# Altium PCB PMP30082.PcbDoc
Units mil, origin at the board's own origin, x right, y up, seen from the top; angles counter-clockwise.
Board outline 2800 x 3100 mil, 2 copper layers (Top Layer, Bottom Layer), stack 62 mil thick; 55 components, 28 nets, 134 pads, 39 vias.
Unrouted connection lines stored in the file: 1.
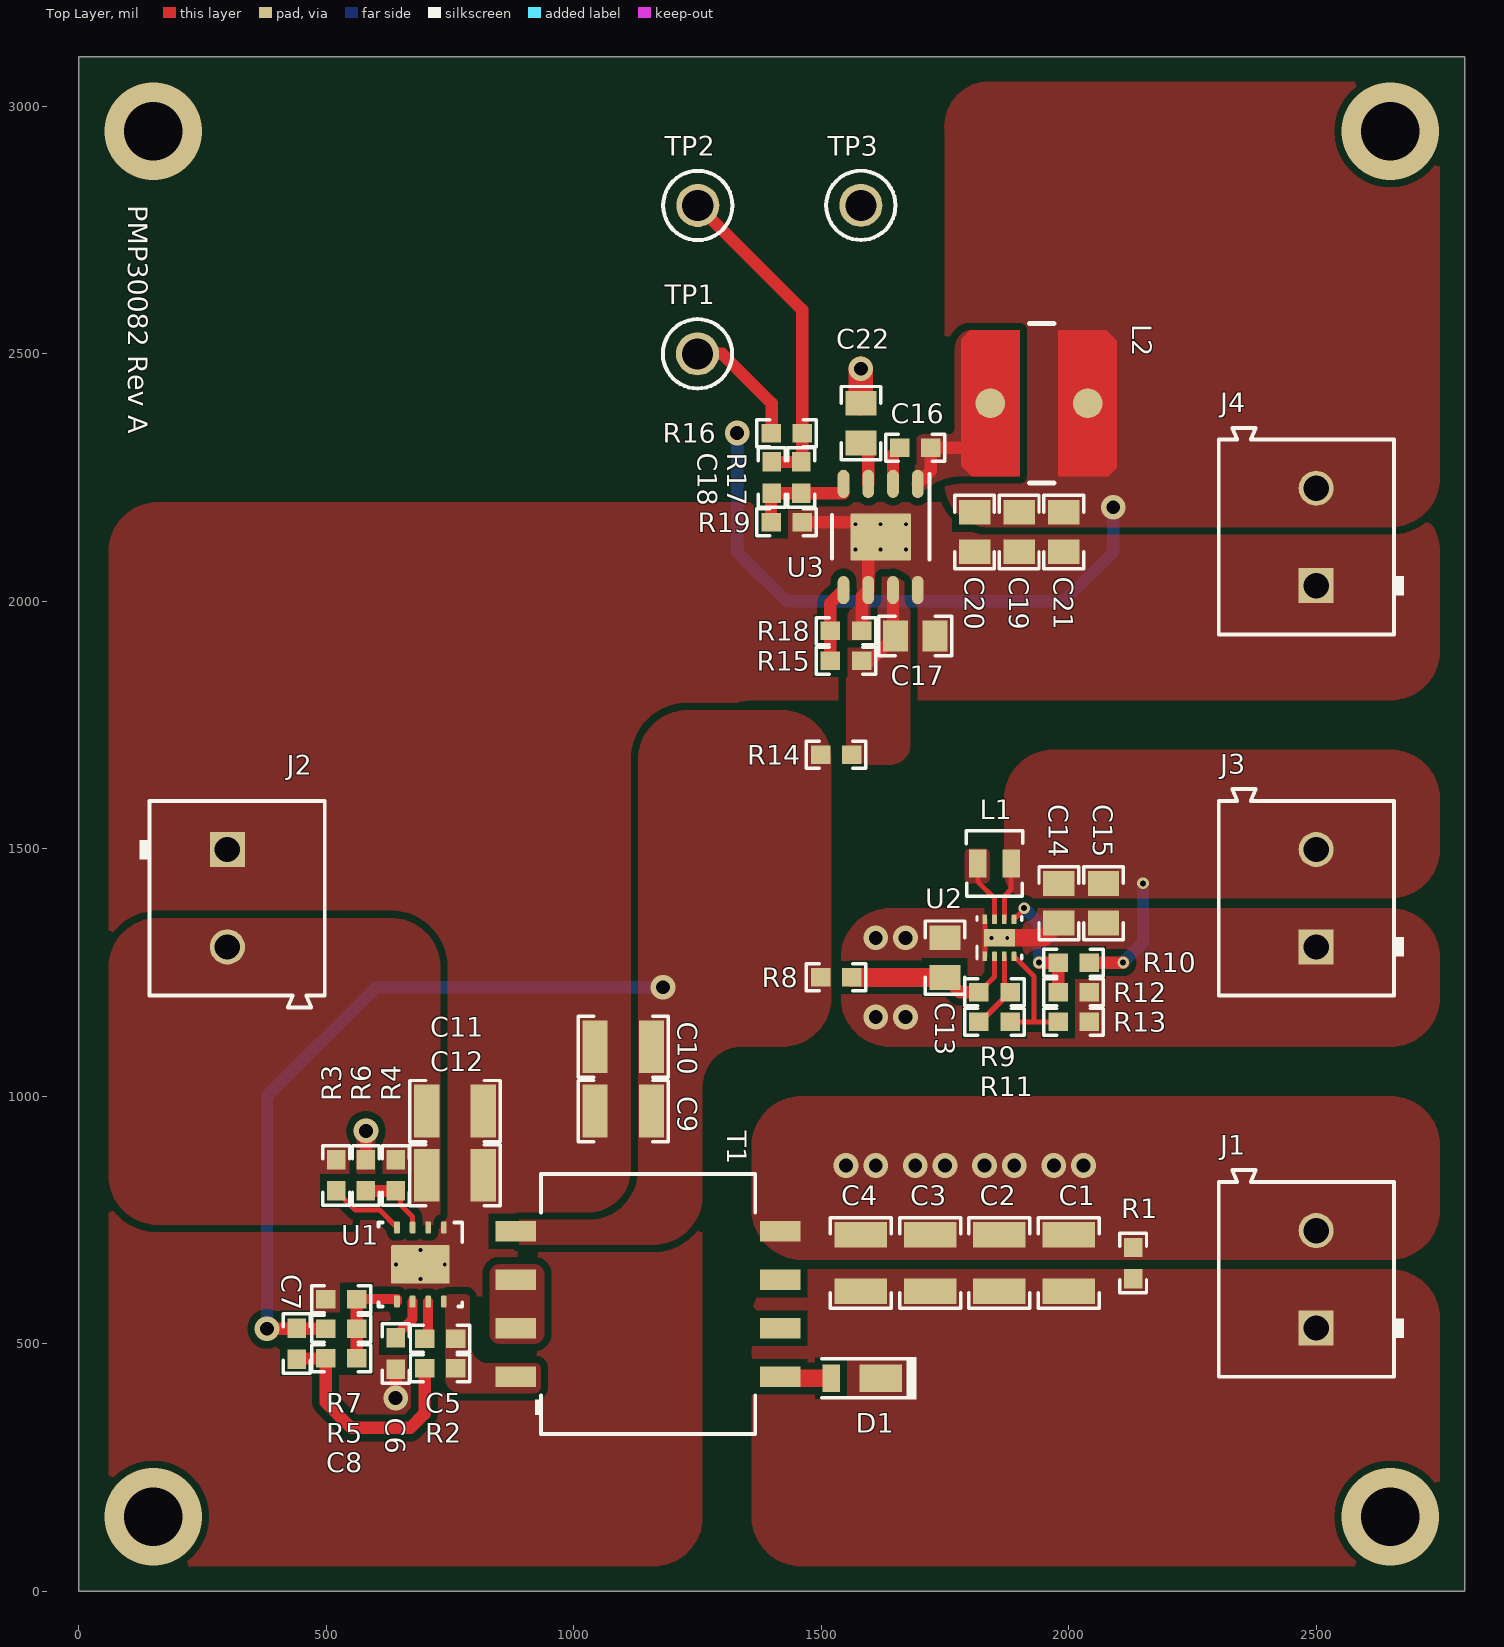
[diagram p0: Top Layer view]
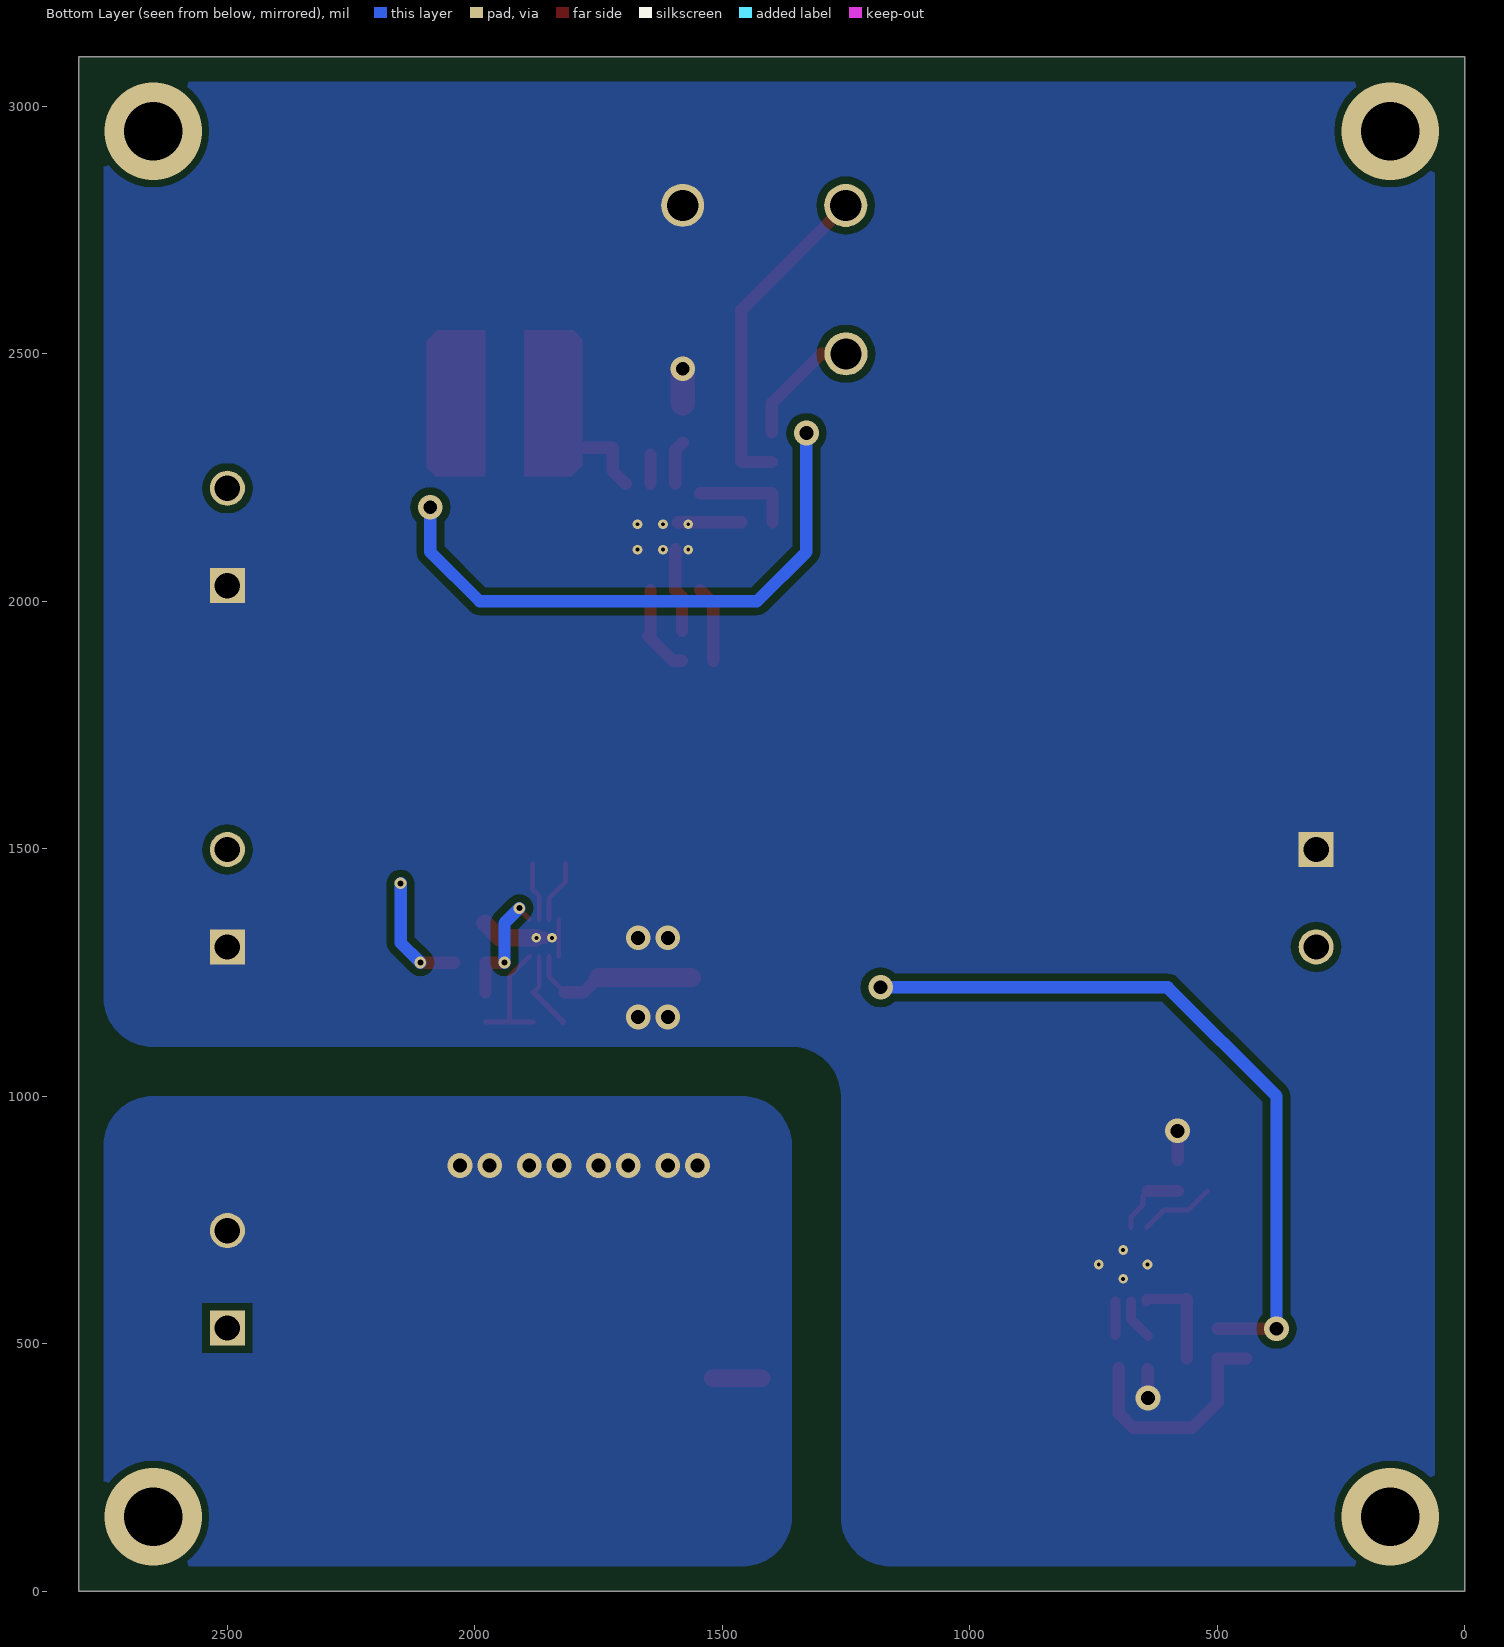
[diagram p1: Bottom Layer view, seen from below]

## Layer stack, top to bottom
Top Solder: solder mask 0.4, Solder Resist, Dk 3.5
Top Layer: signal copper 1.4
Dielectric1: core 59.2, FR-4, Dk 4.8
Bottom Layer: signal copper 1.4
Bottom Solder: solder mask 0.4, Solder Resist, Dk 3.5

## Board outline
0,3100 2800,3100 2800,0 0,0 0,3100

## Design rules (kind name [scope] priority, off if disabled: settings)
AcuteAngle [All] p1: minimum=4.50000000000000E+0001 checktracksonly=FALSE
AssemblyTestPointUsage [All] p1: valid=2
Clearance Clearance_Keepouts [((IsTrack Or IsArc) And Not InPoly) And IsFree and IsKeepOut vs ((IsTrack Or IsArc) And Not InPoly) And IsFree and IsKeepOut] p1: gap=0
Clearance Clearance_BoardEdge_MountingHoles [OnCopper and InComponentClass('Mounting Holes') vs IsKeepOut] p2: gap=40
Clearance Clearance_BoardEdge_Poly [OnCopper and InPoly vs IsKeepOut] p3: gap=25
Clearance Clearance_BoardEdge [OnCopper and Not InComponentClass('Logo') and not InComponentClass('FiducialMark') and not InRegion(1000,500,4000,800) and Not IsKeepout vs IsKeepOut] p4: gap=75
Clearance Clearance_Poly [InPolygon] p5: gap=15
Clearance [All] p6: gap=7.87
ComponentClearance ComponentClearance_MountingHoles_FiducialMarks [InComponentClass('Mounting Holes') vs InComponentClass('FiducialMark')] p1: gap=50 collisioncheckmode=3 verticalgap=10 showdistances=FALSE
ComponentClearance ComponentClearance_Shunt [InComponentClass('Header') vs InComponentClass('Shunt')] p2: gap=0 collisioncheckmode=3 verticalgap=0 showdistances=FALSE
ComponentClearance ComponentClearance_Logo [InComponentClass('Logo')] p3: gap=50 collisioncheckmode=3 verticalgap=10 showdistances=FALSE
ComponentClearance ComponentClearance_ScrewToNut [(HasFootprint('NY PMS 440 0025 PH')) vs (HasFootprint('Keystone_1902C'))] p4: gap=5 collisioncheckmode=3 verticalgap=10 showdistances=FALSE
ComponentClearance ComponentClearance_MountingHoles [InComponentClass('Mounting Holes')] p5: gap=250 collisioncheckmode=3 verticalgap=100000 showdistances=FALSE
ComponentClearance ComponentClearance_SmallPassives [HasFootprint('0201*') or HasFootprint('0402*') or HasFootprint('0508') or HasFootprint('0603*') or HasFootprint('0612') or HasFootprint('0805*') or HasFootprint('0815*') or HasFootprint('0830*') or HasFootprint('1206*') or HasFootprint('1210*') or HasFootprint('1808*') or HasFootprint('1812*') or HasFootprint('1825*') or HasFootprint('2010*') or HasFootprint('2220*') or HasFootprint('2225*') or HasFootprint('2512*') or HasFootprint('2728*') or HasFootprint('3518*') vs HasFootprint('0201*') or HasFootprint('0402*') or HasFootprint('0508') or HasFootprint('0603*') or HasFootprint('0612') or HasFootprint('0805*') or HasFootprint('0815*') or HasFootprint('0830*') or HasFootprint('1206*') or HasFootprint('1210*') or HasFootprint('1808*') or HasFootprint('1812*') or HasFootprint('1825*') or HasFootprint('2010*') or HasFootprint('2220*') or HasFootprint('2225*') or HasFootprint('2512*') or HasFootprint('2728*') or HasFootprint('3518*')] p6: gap=20 collisioncheckmode=3 verticalgap=10 showdistances=FALSE
ComponentClearance ComponentClearance_THtoSMT [IsThruComponent vs IsSMTComponent] p7: gap=100 collisioncheckmode=3 verticalgap=30 showdistances=FALSE
ComponentClearance ComponentClearance_THtoTH [IsThruComponent vs IsThruComponent] p8: gap=118.11 collisioncheckmode=3 verticalgap=30 showdistances=FALSE
ComponentClearance [All] p9: gap=40 collisioncheckmode=3 verticalgap=10 showdistances=FALSE
DiffPairsRouting [All] p1: maxlimit=100 minlimit=10 mostfreqgap=10 toplayer_minwidth=15 toplayer_maxwidth=15 toplayer_prefwidth=15 bottomlayer_minwidth=15 bottomlayer_maxwidth=15 bottomlayer_prefwidth=15 maxuncoupledlength=1000
FabricationTestPointUsage TestPointUsage [All] p1: valid=2 allowmultiple=FALSE
FabricationTestpoint Testpoint [All] p1: side=3 testpointundercomponent=TRUE minsize=40 maxsize=100 preferedsize=60 minholesize=0 maxholesize=40 preferedholesize=32 testpointgrid=1 allowsidetop=TRUE allowsidebottom=TRUE usegrid=TRUE gridtolerance=0.01
FanoutControl Fanout_LCC [IsLCC] p1: bgadir=Out bgaviamode=Centered fanoutstyle=Auto fanoutdirection=Alternating viagrid=1 // Fanout_LCC (Default Rule)
FanoutControl Fanout_BGA [IsBGA] p2: bgadir=Out bgaviamode=Centered fanoutstyle=Auto fanoutdirection=Alternating viagrid=1 // Fanout_BGA (Default Rule)
FanoutControl Fanout_Default [All] p4: bgadir=Out bgaviamode=Centered fanoutstyle=Auto fanoutdirection=Alternating viagrid=1 // Fanout_Default (Default Rule)
FanoutControl Fanout_Small [(CompPinCount < 5)] p5: bgadir=Out bgaviamode=Centered fanoutstyle=Auto fanoutdirection=OutThenIn viagrid=1 // Fanout_Small (Default Rule)
HoleSize [All] p1: absolutevalues=TRUE maxlimit=251 minlimit=8 maxpercent=80.000 minpercent=20.000
MinimumAnnularRing MinimumAnnularRing_ThermalPadVias [IsVia and InAnyComponent] p1: minimumring=5.91
MinimumAnnularRing [All] p2: minimumring=9
MinimumSolderMaskSliver MinimumSolderMaskSliver_Logo [InComponentClass('Logo') vs InComponentClass('Logo')] p1: minsoldermaskwidth=0.7
MinimumSolderMaskSliver [All] p2: minsoldermaskwidth=3.94
PlaneConnect [All] p1: planeconnectstyle=Relief reliefexpansion=10 reliefentries=4 reliefconductorwidth=10 reliefairgap=10
PolygonConnect [All] p1: connectstyle=Direct reliefconductorwidth=10 reliefentries=4 polygonreliefangle="90 Angle" airgapwidth=10
RoutingVias ThermalPadVias [IsVia and InAnyComponent] p1: holewidth=7.87 width=19.68 viastyle="Through Hole" minholewidth=7.87 minwidth=19.68 maxholewidth=12.99 maxwidth=23.62
RoutingVias [All] p2: holewidth=16 width=34 viastyle="Through Hole" minholewidth=7.87 minwidth=26 maxholewidth=40 maxwidth=65
SilkToBoardRegionClearance [Not ((IsComment or IsDesignator) And (Hide <> 'False')) and not InRegion(1000,500,4000,800)] p1:
SilkToSilkClearance SilkToSilkClearance_Pb-FreeLogo [(HasFootprint('Pb-Free_Overlay_Medium') OR HasFootprint('Pb-Free_Overlay_Small')) vs (HasFootprint('Pb-Free_Overlay_Medium') OR HasFootprint('Pb-Free_Overlay_Small'))] p1: silktosilkclearance=0
SilkToSilkClearance [All] p2: silktosilkclearance=4
SilkToSolderMaskClearance SilkToComonentPadClearance [IsPad and InAnycomponent] p1: minsilkscreentomaskgap=5 clearancetoexposedcopper=TRUE
SilkToSolderMaskClearance "Silk to Solder Mask Opening" [All] p2: minsilkscreentomaskgap=4 clearancetoexposedcopper=FALSE
SolderMaskExpansion [All] p1: expansion=1.97
Width [All] p1: maxlimit=100 minlimit=6 preferedwidth=10 checkconnectedcopper=TRUE
15 further rules are at their usual default settings.

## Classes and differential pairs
component class "PMP30082_1_RevA - Circuit": C1 C2 C3 C4 C5 C6 C7 C8 C9 C10 C11 C12 D1 J1 J2 R1 R2 R3 R4 R5 R6 R7 T1 U1
component class "PMP30082_2_RevA - Circuit": C16 C17 C18 C19 C20 C21 C22 J4 L2 R14 R15 R16 R17 R18 R19 TP1 TP2 TP3 U3
component class "PMP30082_3_RevA - Circuit": C13 C14 C15 J3 L1 R8 R9 R10 R11 R12 R13 U2

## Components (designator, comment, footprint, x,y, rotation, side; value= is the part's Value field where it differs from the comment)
C1 "GRM32ER61H106KA12L" 1210_270 2000,662.76 r270 top
C2 "GRM32ER61H106KA12L" 1210_270 1860,662.76 r270 top
C3 "GRM32ER61H106KA12L" 1210_270 1720,662.76 r270 top
C4 "GRM32ER61H106KA12L" 1210_270 1580,662.76 r270 top
C5 "GCM188R71H103KA37D" 0603 730,510 r180 top
C6 "GRM188R71C105KA12D" 0603 640,480 r90 top
C7 "GRM188R70J473KA01D" 0603 440,500 r270 top
C8 "GCM188R71H104KA57D" 0603 530,470 r0 top
C9 "GRM32ER61E226KE15L" 1210_270 1100,970 r180 top
C10 "GRM32ER61E226KE15L" 1210_270 1100,1100 r180 top
C11 "GRM32ER72A225KA35L" 1210_270 760,970 r0 top
C12 "GRM32ER72A225KA35L" 1210_270 760,840 r0 top
C13 "GRM21BR61E225KA12L" 0805_HV 1750,1280 r90 top
C14 "GRM21BR70J106KE76L" 0805_HV 1980,1390 r270 top
C15 "GRM21BR70J106KE76L" 0805_HV 2070,1390 r270 top
C16 "GRM188R71C474KA88D" 0603 1690,2310 r180 top
C17 "GRM21BC71E106KE11L" 0805_HV 1690,1930 r0 top
C18 "GRM1885C2A151JA01D" 0603 1400,2250 r270 top
C19 "GRM21BR61A226ME44L" 0805_HV 1900,2140 r270 top
C20 "GRM21BR61A226ME44L" 0805_HV 1810,2140 r270 top
C21 "GRM21BR61A226ME44L" 0805_HV 1990,2140 r270 top
C22 "GRM21BR71C475KA73L" 0805_HV 1580,2360 r90 top
D1 "DFLS1200-7" PowerDI123 1570,430 r180 top
J1 "691 101 710 002" Wurth_691101710002 2500,630 r90 top
J2 "691 101 710 002" Wurth_691101710002 300,1400 r270 top
J3 "691 101 710 002" Wurth_691101710002 2500,1400 r90 top
J4 "691 101 710 002" Wurth_691101710002 2500,2130 r90 top
L1 "VLF302515MT-150M" VLF302515MT 1850,1470 r0 top
L2 "744775147" WE-PD2-L 1940,2400 r0 top
R1 "CRCW060312K1FKEA" 0603 2130,662.76 r90 top
R2 "CRCW060310K0FKEA" 0603 730,450 r180 top
R3 "CRCW0603301KFKEA" 0603 520,840 r270 top
R4 "ERJ-3GEY0R00V" 0603 640,840 r90 top
R5 "CRCW060344K2FKEA" 0603 530,530 r180 top
R6 "CRCW060310K0FKEA" 0603 580,840 r270 top
R7 "CPF0603B4K99E" 0603 530,590 r0 top
R8 "ERJ-3GEY0R00V" 0603 1530,1240 r180 top
R9 "ERJ-3GEY0R00V" 0603 1850,1210 r180 top
R10 "CRCW0603180KJNEA" 0603 2010,1270 r0 top
R11 "ERJ-3GEY0R00V" 0603 1850,1150 r180 top
R12 "CRCW060357K6FKEA" 0603 2010,1210 r180 top
R13 "ERJ-3GEY0R00V" 0603 2010,1150 r180 top
R14 "ERJ-3GEY0R00V" 0603 1530,1690 r180 top
R15 "ERJ-3GEY0R00V" 0603 1550,1880 r180 top
R16 "CRCW060349R9FKEA" 0603 1430,2340 r180 top
R17 "CRCW060349K9FKEA" 0603 1460,2250 r90 top
R18 "ERJ-3GEY0R00V" 0603 1550,1940 r180 top
R19 "CRCW060312K4FKEA" 0603 1430,2160 r180 top
T1 "750370599" Wurth_750370599 1150,580 r90 top
TP1 "5010" Keystone5010 1250,2500 r90 top
TP2 "5014" Keystone5014 1250.5,2799.87 r90 top
TP3 "5011" Keystone5011 1580,2800 r90 top
U1 "LM5017SDX/NOPB" NGU0008B 690,660 r270 top
U2 "TPS62125DSGR" DSG0008A 1860,1320 r90 top
U3 "LMR23610ADDAR" DDA0008E_N 1620,2130 r270 top

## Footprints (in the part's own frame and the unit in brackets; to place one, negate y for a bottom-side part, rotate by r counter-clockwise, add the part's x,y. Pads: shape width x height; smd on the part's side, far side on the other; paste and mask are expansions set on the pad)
0603 [mm] "0603 from SM-752 data"
  rect 1x0.95 smd: 1(-0.8,0) 2(0.8,0)
  silkscreen extent -1.52,-0.69 1.52,0.69, body extent -0.87,-0.47 0.87,0.47, height 1
0805_HV [mil] "0805 with 30mil clearance between pads"
  rect 50x63 smd: 1(-40,0) 2(40,0)
  silkscreen extent -74,-40 74,40, body extent -43,-29 43,29, height 57
1210_270 [mm] "1210"
  rect 1.3x2.7 smd: 1(-1.45,0) 2(1.45,0)
  silkscreen extent -2.32,-1.57 2.32,1.57, body extent -1.7,-1.35 1.7,1.35, height 2.7
DDA0008E_N [mm]
  rrect100% 1.45x0.6 smd: 1(-2.725,1.905) 2(-2.725,0.635) 3(-2.725,-0.635) 4(-2.725,-1.905) 5(2.725,-1.905) 6(2.725,-0.635) 7(2.725,0.635) 8(2.725,1.905)
  rrect4% 2.4x3.1 smd: 9(0,0)
  silkscreen extent -3.22,-2.5 1.15,2.5, body extent -3.01,-2.45 3.01,2.45, height 1.7
DSG0008A [mm] "SON, 8-Leads, Body 2x2mm, Pitch 0.5mm, Thermal Pad 1.6x0.9mm, TI Recommended"
  rrect40% 0.5x0.25 smd: 1(-0.95,0.75) 2(-0.95,0.25) 3(-0.95,-0.25) 4(-0.95,-0.75) 5(0.95,-0.75) 6(0.95,-0.25) 7(0.95,0.25) 8(0.95,0.75)
  rrect11% 0.9x1.6 smd paste-0.45: 9(0,0)
  silkscreen extent -1.07,-1.15 1.07,1.15, body extent -1.05,-1.05 1.05,1.05, height 0.8
Keystone5010 [mil] "Keystone Multipurpose loops"
  round 87 hole 63: 1(0,0)
  silkscreen extent -70,-70 70,70, body extent -63,-63 63,62, height 319
Keystone5011 [mil] "Keystone Multipurpose loops"
  round 87 hole 63: 1(0,0)
  silkscreen extent -70,-70 70,70, body extent -63,-63 63,62, height 319
Keystone5014 [mil] "Keystone Multipurpose loops"
  round 87 hole 63: 1(0,0)
  silkscreen extent -70,-70 70,70, body extent -63,-63 63,62, height 319
NGU0008B [mm] "SON, 8-Leads, Body 4x4mm, Pitch 0.8mm"
  rrect33% 0.6x0.3 smd: 1(-1.9,1.2) 2(-1.9,0.4) 3(-1.9,-0.4) 4(-1.9,-1.2) 5(1.9,-1.2) 6(1.9,-0.4) 7(1.9,0.4) 8(1.9,1.2)
  rrect5% 1.98x3 smd paste-1.5: 9(0,0)
  silkscreen extent -2.15,-2.15 2.15,2.15, body extent -2.05,-2.05 2.05,2.05, height 0.81
PowerDI123 [mm] "Diodes Inc recommended land pattern, document number DS30628 Rev. 6-2"
  rect 2.2x1.4 smd: 1(-1.275,0)
  rect 0.9x1.4 smd: 2(1.275,0)
  silkscreen extent -3.1,-1.09 1.76,1.09, body extent -2.38,-0.97 1.52,0.96, height 1
VLF302515MT [mm] "TDK"
  rect 0.9x1.45 smd: 1(-0.85,0) 2(0.85,0)
  silkscreen extent -1.45,-1.68 1.45,1.68, body extent -1.35,-1.6 1.35,1.6, height 1.5
WE-PD2-L [mil] "WE, Inductor"
  round 60 smd: 1(-98.43,0) 2(98.43,0)
  Top Layer region: 39.37,147.64 39.37,-147.64 139.76,-147.64 157.48,-129.92 157.48,125.98 135.83,147.64
  Top Layer region: -39.37,-147.64 -39.37,147.64 -139.76,147.64 -157.48,129.92 -157.48,-125.98 -135.83,-147.64
  silkscreen extent -20,-161 30,161, body extent -157,-144 159,144, height 217
Wurth_750370599 [mm] "SMD, 8-Leads, Body 15.24x11mm, Pitch 2.49mm"
  rect 1.07x2.08 smd: 1(-3.735,6.78) 2(-1.245,6.78) 3(1.245,6.78) 4(3.735,6.78) 5(3.735,-6.78) 6(1.245,-6.78) 7(-1.245,-6.78) 8(-3.735,-6.78)
  silkscreen extent -6.67,-5.5 6.67,5.8, body extent -6.67,-7.62 6.67,7.62, height 11.44
Wurth_691101710002 [mm] "Terminal Block, 5 mm, 2x1, TH"
  rect 1.8x1.8 hole 1.3: 1(-2.5,0)
  round 1.8 hole 1.3: 2(2.5,0)
  silkscreen extent -5,-4.5 5.6,5, body extent -5.6,-4 5.6,5, height 12.5

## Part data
C1 C2 C3 C4: "CAP, CERM, 10 µF, 50 V, +/- 10%, X5R, 1210"
C5: "CAP, CERM, 0.01 µF, 50 V, +/- 10%, X7R, AEC-Q200 Grade 1, 0603"
C6: "CAP, CERM, 1 µF, 16 V, +/- 10%, X7R, 0603"
C7: "CAP, CERM, 0.047 µF, 6.3 V, +/- 10%, X7R, 0603"
C8: "CAP, CERM, 0.1 µF, 50 V, +/- 10%, X7R, 0603"
C9 C10: "CAP, CERM, 22 µF, 25 V, +/- 10%, X5R, 1210"
C11 C12: "CAP, CERM, 2.2 µF, 100 V, +/- 10%, X7R, 1210"
C13: "CAP, CERM, 2.2 µF, 25 V, +/- 10%, X5R, 0805"
C14 C15: "CAP, CERM, 10 µF, 6.3 V, +/- 10%, X7R, 0805"
C16: "CAP, CERM, 0.47 µF, 16 V, +/- 10%, X7R, 0603"
C17: "CAP, CERM, 10 µF, 25 V, +/- 10%, X7S, 0805"
C18: "CAP, CERM, 150 pF, 100 V, +/- 5%, C0G/NP0, 0603"
C19 C20 C21: "CAP, CERM, 22 µF, 10 V, +/- 20%, X5R, 0805"
C22: "CAP, CERM, 4.7 µF, 16 V, +/- 10%, X7R, 0805"
D1: "Diode, Schottky, 200 V, 1 A, PowerDI123"
J1 J2 J3 J4: "Terminal Block, 5 mm, 2x1, Tin, TH"
L1: "Inductor, Shielded, Ferrite, 15 µH, 0.56 A, 0.275 ohm, SMD"
L2: "Inductor, Shielded Drum Core, Ferrite, 47 µH, 1.17 A, 0.18 ohm, SMD"
R1: "RES, 12.1 k, 1%, 0.1 W, 0603"
R2 R6: "RES, 10.0 k, 1%, 0.1 W, 0603"
R3: "RES, 301 k, 1%, 0.1 W, 0603"
R4 R8 R9 R11 R13 R14 R15 R18: "RES, 0, 5%, 0.1 W, 0603"
R5: "RES, 44.2 k, 1%, 0.1 W, 0603"
R7: "RES, 4.99 k, 0.1%, 0.063 W, 0603"
R10: "RES, 180 k, 5%, 0.1 W, 0603"
R12: "RES, 57.6 k, 1%, 0.1 W, 0603"
R16: "RES, 49.9, 1%, 0.1 W, 0603"
R17: "RES, 49.9 k, 1%, 0.1 W, 0603"
R19: "RES, 12.4 k, 1%, 0.1 W, 0603"
T1: "Transformer, 250 uH, SMT"
TP1: "Test Point, Multipurpose, Red, TH"
TP2: "Test Point, Multipurpose, Yellow, TH"
TP3: "Test Point, Multipurpose, Black, TH"
U1: "100V, 600mA Constant On-Time Synchronous Buck Regulator, NGU0008B"
U2: "3V-17V, 300mA Step Down Converter With Adjustable Enable Threshold And Hysteresis, DSG0008A"
U3: "SIMPLE SWITCHER 36 V, 1 A Synchronous Step-Down Converter, DDA0008E"

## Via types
v1: diameter 50, hole 28, Top Layer to Bottom Layer, 19 vias
v2: diameter 19.68, hole 7.87, Top Layer to Bottom Layer, 6 vias
v3: diameter 19.68, hole 7.87, Top Layer to Bottom Layer, tented top, 6 vias
v4: diameter 23.62, hole 11.81, Top Layer to Bottom Layer, 4 vias
v5: diameter 196.85, hole 118.11, Top Layer to Bottom Layer, 4 vias

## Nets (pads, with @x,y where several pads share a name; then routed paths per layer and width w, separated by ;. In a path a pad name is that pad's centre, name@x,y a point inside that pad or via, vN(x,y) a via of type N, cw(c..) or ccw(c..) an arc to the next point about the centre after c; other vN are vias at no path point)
"3.3V @ 100MA": C14.1 C15.1 J3.2 L1.2 R10.2 U2.6 | length 363.3
  Top Layer w10: U2.6 1869.84,1403.9 1883.46,1417.52 L1.2
  Top Layer w25: R10.2 v4(2110,1270)
  Bottom Layer w25: v4(2110,1270) 2150,1310 v4(2150,1430)
"5V @ 400MA": C19.1 C20.1 C21.1 J4.2 L2.2 R16.2 TP1.1 | length 1422.8
  Top Layer w25: TP1.1 1300,2500 1400,2400 R16.2@1400,2341.5
  Bottom Layer w25: v1(1330,2340) 1330,2100 1430,2000 1990,2000 2090,2100 v1(2090,2190)
"12V @ 250MA": C7.1 C9.1 C10.1 R5.2 R8.2 R14.2 T1.4 | length 1479.6
  Top Layer w25: v1(380,530) R5.2
  Bottom Layer w25: v1(380,530) 380,1000 600,1220 v1(1180,1220)
"24VOUT @ 160MA": C1.2 C2.2 C3.2 C4.2 D1.1 J1.1 R1.1
48-72VIN: C11.1 C12.1 J2.2 R3.1 R4.2 U1.2
GND: C6.1 C9.2 C10.2 C11.2 C12.2 C13.2 C14.2 C15.2 C17.2 C19.2 C20.2 C21.2 C22.2 J2.1 J3.1 J4.1 R6.1 R7.1 R12.1 R13.1 R18.1 R19.1 TP3.1 U1.1 U1.9 U2.1 U2.8 U2.9 U3.6 U3.8 U3.9 | length 722.9
  Top Layer w10: U2.1 U2.9@1830.47,1320 ; U2.8 U2.9@1830.47,1320 ; U2.9 v2(1844.25,1320) U2.9@1830.47,1320
  Top Layer w25: R6.1 v1(580,930) ; v1(640,390) C6.1 ; R19.1 U3.9@1590,2160 ; R18.1 1581.5,2009.21 U3.6 U3.9@1595,2105 ; U2.9 v2(1875.75,1320)
  Top Layer w35: v2(1875.75,1320) 1950,1320 C14.2
  Top Layer w50: C22.2 v1(1580,2470)
  other v1: 1610,1160 1670,1160 1610,1320 1670,1320
  other v2: 690,630.87 640.79,660 739.21,660 690,689.13
  other v3: 1568.82,2104.41 1620,2104.41 1671.18,2104.41 1568.82,2155.59 1620,2155.59 1671.18,2155.59
ISOGND: C1.1 C2.1 C3.1 C4.1 J1.2 R1.2 T1.5
  other v1: 1550,860 1610,860 1690,860 1750,860 1830,860 1890,860 1970,860 2030,860
NetC5_1: C5.1 R2.1 T1.1 U1.8
NetC5_2: C5.2 U1.7 | length 68
  Top Layer w20: C5.2@705.75,517.24 U1.7
NetC6_2: C6.2 U1.6 | length 84.2
  Top Layer w20: C6.2@640,515.16 674.25,549.41 U1.6
NetC7_2: C7.2 C8.1 R2.2 | length 470.1
  Top Layer w25: C7.2@441.5,470 C8.1 498.5,381.5 550,330 670,330 698.5,358.5 R2.2
NetC8_2: C8.2 R5.1 R7.2 U1.5 | length 206.1
  Top Layer w20: R7.2 642.76,590 U1.5
  Top Layer w25: C8.2 R7.2
NetC13_1: C13.1 R8.1 R9.2 U2.2 | length 355.1
  Top Layer w10: R9.2 1850,1241.5 1850,1282.44 U2.2
  Top Layer w25: C13.1 1780,1210 R9.2
  Top Layer w38: R8.1 C13.1
NetC16_1: C16.1 L2.1 U3.1 | length 172.2
  Top Layer w25: U3.1 1721.5,2263.78 C16.1 1810,2310
NetC16_2: C16.2 U3.2 | length 59.2
  Top Layer w25: U3.2 C16.2@1645,2296.5
NetC17_1: C17.1 R14.1 R15.1 U3.7 | length 176.9
  Top Layer w25: R15.1 1600,1880 C17.1 ; C17.1@1645,1935 U3.7
NetC18_1: C18.1 R16.1 R17.2 TP2.1 | length 664.3
  Top Layer w25: TP2.1 1461.5,2588.88 R16.1 R17.2@1461.5,2282.99 ; C18.1 R17.2
NetC18_2: C18.2 R17.1 R19.2 U3.4 | length 204.1
  Top Layer w25: R19.2 1398.5,2217.01 C18.2 R17.1 U3.4@1545,2218.5
NetC22_1: C22.1 U3.3 | length 88.9
  Top Layer w25: C22.1 1595,2305 U3.3
NetD1_2: D1.2 T1.8 | length 99.9
  Top Layer w35: T1.8@1419.88,430 D1.2
NetL1_1: L1.1 U2.7 | length 126.5
  Top Layer w10: L1.1 1816.54,1433.46 1850.16,1399.84 U2.7
NetR3_2: R3.2 U1.4 | length 153.3
  Top Layer w10: R3.2 558.5,770 607.56,770 U1.4
NetR4_1: R4.1 R6.2 U1.3 | length 147.9
  Top Layer w10: R4.1 650,798.5 650,780 674.25,755.75 U1.3
  Top Layer w25: R6.2 R4.1
NetR9_1: R9.1 R11.2 U2.3 | length 162.3
  Top Layer w10: U2.3 1869.84,1221.65 R9.1
  Top Layer w12: R11.2@1821.5,1150 R9.1
NetR10_1: R10.1 R12.2 U2.5 | length 249.9
  Top Layer w10: U2.5 v4@1910,1377.87
  Top Layer w25: v4(1940,1270) R10.1 R12.2
  Bottom Layer w25: v4(1910,1380) 1940,1350 v4(1940,1270)
NetR11_1: R11.1 R13.2 U2.4 | length 246.4
  Top Layer w10: R11.1 1930,1150 ; U2.4 1930,1242.13 1930,1150 ; R13.2 1930,1150
NetR15_2: R15.2 R18.2 U3.5 | length 153.7
  Top Layer w25: R15.2 R18.2 1518.5,1996.22 U3.5
NetT1_2: T1.2 T1.3
pads on no net: T1.6 T1.7
copper on no net:
  other v5: 150,150 2650,150 150,2950 2650,2950

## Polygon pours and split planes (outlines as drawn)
NetL1_1 on Top Layer "NETL1_1_L01_P068" (solid, remove dead copper, pour order 68): 1790,1460 1790,1480 1790,1490 cw(c1800,1490) 1800,1500 1830,1500 cw(c1830,1490) 1840,1490 1840,1440 cw(c1830,1440) 1830,1430 1800,1430 cw(c1800,1440) 1790,1440 1790,1460
NetT1_2 on Top Layer "NETT1_2_L01_P026" (solid, remove dead copper, pour order 26): 830,580 830,640 cw(c850,640) 850,660 920,660 cw(c920,640) 940,640 940,520 cw(c920,520) 920,500 850,500 cw(c850,520) 830,520 830,580
"3.3V @ 100MA" on Top Layer "Top Layer-No Net 5" (solid, remove dead copper, pour order 22): 1870,1540 1870,1600 cw(c1970,1600) 1970,1700 2340,1700 2650,1700 cw(c2650,1600) 2750,1600 2750,1540 2750,1500 cw(c2650,1500) 2650,1400 2080,1400 1920,1400 cw(c1920,1450) 1870,1450 1870,1610
"12V @ 250MA" on Top Layer "Top Layer-No Net 4" (solid, remove dead copper, pour order 18): 890,750 1030,750 ccw(c1030,850) 1130,850 1130,920 1130,1680 cw(c1230,1680) 1230,1780 1300,1780 1420,1780 cw(c1420,1680) 1520,1680 1520,1211.46 1520,1200 cw(c1420,1200) 1420,1100 1340,1100 ccw(c1340,1020) 1260,1020 1260,860 1260,800 cw(c1160,800) 1160,700 890,700 890,750
NetC16_1 on Top Layer "Top Layer-No Net 3" (solid, remove dead copper, pour order 2): 1704.5,2220 1707.57,2223.07 cw(c1778.28,2152.36) 1778.28,2252.36 1804.17,2252.36 1900.63,2252.36 1900.63,2547.64 1800.96,2547.64 ccw(c1800.96,2521.56) 1782.52,2540 ccw(c1812.74,2509.77) 1770,2509.77 1770,2360 1770,2350 cw(c1757.2,2350) 1757.2,2337.2 1730,2337.2 1707.2,2337.2 ccw(c1707.2,2320) 1690,2320 1690,2230 ccw(c1700,2230) 1700,2220
"5V @ 400MA" on Top Layer "Top Layer-No Net 2" (solid, remove dead copper, pour order 16): 2320,3050 2650,3050 cw(c2650,2950) 2750,2950 2750,2500 2750,2250 cw(c2650,2250) 2650,2150 2200,2150 1830,2150 cw(c1840,2240) 1750,2250 1750,2570 1750,2950 cw(c1840,2960) 1830,3050 2310,3050
ISOGND on Top Layer "Top Layer-No Net 1" (solid, remove dead copper, pour order 6): 1360,870 1360,900 cw(c1460,900) 1460,1000 1800,1000 2650,1000 cw(c2650,900) 2750,900 2750,870 2750,770 cw(c2650,770) 2650,670 2500,670 1460,670 cw(c1460,770) 1360,770 1360,870
"24VOUT @ 160MA" on Top Layer "Top Layer-No Net" (solid, remove dead copper, pour order 4): 1360,230 1360,150 ccw(c1460,150) 1460,50 2100,50 2650,50 ccw(c2650,150) 2750,150 2750,230 2750,550 ccw(c2650,550) 2650,650 1922.99,650 1460,650 ccw(c1460,550) 1360,550 1360,230
NetC5_1 on Top Layer "Top Layer-No Net 7" (solid, remove dead copper, pour order 36): 789.98,520 789.98,500 ccw(c829.98,500) 829.98,460 870,460 923.46,460 cw(c923.46,450) 933.46,450 933.46,413.46 cw(c920,413.46) 920,400 771.3,400 cw(c771.3,431.3) 740,431.3 740,590 cw(c750,590) 750,600 780,600 cw(c780,590) 790,590 790,501.02 ccw(c791.02,501.02) 791.02,500
48-72VIN on Top Layer "Top Layer-No Net 8" (solid, remove dead copper, pour order 44): 60,820 60,1090 60,1260 cw(c160,1260) 160,1360 470,1360 630,1360 cw(c630,1260) 730,1260 730,916.85 730,740.71 360.71,740.71 ccw(c360.71,740) 360,740 230,740 160,740 cw(c160,840) 60,840 60,1270
NetC17_1 on Top Layer "Top Layer-No Net 9" (solid, remove dead copper, pour order 46): 1550,1720 1550,2005 cw(c1595,2005) 1595,2050 1640,2050 cw(c1640,2010) 1680,2010 1680,1710 cw(c1640,1710) 1640,1670 1600,1670 cw(c1600,1720)
GND on Top Layer "Top Layer-No Net 6" (solid, remove dead copper, pour order 24): 2180,1380 2650,1380 cw(c2650,1280) 2750,1280 2750,1230 2750,1200 cw(c2650,1200) 2650,1100 2200,1100 1640,1100 cw(c1640,1200) 1540,1200 1540,1258.7 1540,1280 cw(c1640,1280) 1640,1380 2180,1380
GND on Top Layer "Top Layer-No Net 10" (solid, remove dead copper, pour order 60): 60,600 60,150 ccw(c160,150) 160,50 730,50 1160,50 ccw(c1160,150) 1260,150 1260,700 1260,1700 cw(c1360,1700) 1360,1800 2100,1800 2650,1800 ccw(c2650,1900) 2750,1900 2750,2000 2750,2100 ccw(c2650,2100) 2650,2200 1100,2200 160,2200 ccw(c160,2100) 60,2100 60,600
ISOGND on Bottom Layer "Bottom Layer-No Net" (solid, remove dead copper, pour order 14): 1360,206.21 1360,150 ccw(c1460,150) 1460,50 2000,50 2650,50 ccw(c2650,150) 2750,150 2750,500 2750,900 ccw(c2650,900) 2650,1000 1700,1000 1460,1000 ccw(c1460,900) 1360,900 1360,206.21
GND on Bottom Layer "Top Layer-No Net 11" (solid, remove dead copper, pour order 62): 1260,300 1260,150 cw(c1160,150) 1160,50 600,50 160,50 cw(c160,150) 60,150 60,500 60,2950 cw(c160,2950) 160,3050 500,3050 2650,3050 cw(c2650,2950) 2750,2950 2750,2920 2750,1200 cw(c2650,1200) 2650,1100 2500,1100 1360,1100 ccw(c1360,1000) 1260,1000 1260,300

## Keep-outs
Keep-Out Layer:
  text ".Layer_Name" at 577,-858.49 h60

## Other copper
Top Layer:
  text ".Layer_Name" at 577,-858.49 h60
Bottom Layer:
  text ".Layer_Name" at 577,-858.49 h60

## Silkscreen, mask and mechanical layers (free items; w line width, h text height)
Top Overlay:
  text "PMP30082 Rev A" at 100,2800 h40 r270
  text ".Layer_Name" at 577,-858.49 h60
Bottom Overlay:
  text ".Layer_Name" at 577,-858.49 h60
Top Paste:
  text ".Layer_Name" at 577,-858.49 h60
Bottom Paste:
  text ".Layer_Name" at 577,-858.49 h60
Top Solder:
  text "5V" at 2440,2380 h40
  text "GND" at 2450,1840 h40
  text "GND" at 150,1650 h40
  text "3.3V" at 2440,1650 h40
  text "GND" at 2450,1130 h40
  text "48VIN" at 150,1120 h40
  text "ISOGND" at 2460,940 h40
  text "24VOUT" at 2460,350 h40
  text ".Layer_Name" at 577,-858.49 h60
  text ".Layer_Name" at 577,-858.49 h60
Bottom Solder:
  drawing of 599 lines, arcs and shapes, not listed
  text ".Layer_Name" at 577,-858.49 h60
Drill Guide:
  text ".Layer_Name" at 577,-858.49 h60
M1 Board Outline:
  the board outline again, w47.24
  text ".Layer_Name" at 577,-858.49 h60
M2 Board Dimensions:
  rectangle: 125,-400 500,-275
  rectangle: 0,-275 125,-150
  lines w7: 0,-275 1000,-275 ; 125,-400 125,-150 ; 250,-400 250,-150 ; 500,-400 500,-150 ; 750,-400 750,-150 ; 0,-400 0,-150 1000,-150 1000,-400 0,-400
  text ".Layer_Name" at 577,-858.49 h60
M3 3D STEP Top:
  text ".Layer_Name" at 577,-858.49 h60
M4 3D STEP Bottom:
  text ".Layer_Name" at 577,-858.49 h60
M5 Assembly Top:
  lines w10: -292,-930.17 6308,-930.17 ; -292,-726.83 6310,-726.83 ; -292,-523.5 -292,-1133.5 3713,-1133.5 6310,-1133.5 6310,-523.5 -291.5,-523.5 -291.5,-1133.5 1284,-1133.5 ; 2173,-1133.5 2173,-523.5 ; 3440,-726.83 3440,-523.5 ; 4280,-726.83 4280,-523.5 ; 4902,-1140 4902,-937.17
  text "COMPONENTS MARKED 'DNP' SHOULD NOT BE POPULATED." at 1153.5,-318.5 h60
  text "ASSEMBLY VARIANT:" at 1153,-434 h60
  text ".VariantName" at 2189,-434 h60
  text "PCB VIEWED FROM TOP SIDE" at -228.5,-655.67 h60
  text "BOARD #:" at 2248,-655.67 h60
  text ".PRJ_Number" at 2793.5,-655.67 h60
  text "REV:" at 3638,-655.67 h60
  text ".PCB_Rev" at 3929.5,-655.67 h60
  text "SVN REV:" at 4476,-655.67 h60
  text ".VersionControl_RevNumber" at 4982,-655.67 h60
  text "TID #:" at 2248,-859 h60
  text ".TID" at 2793.5,-859 h60
  text "PLOT NAME =" at -228.5,-1064.34 h60
  text ".plot_File_Name" at 577,-1064.34 h60
  text "GENERATED    :" at 2250,-1064.34 h60
  text ".Print_Date" at 3119.5,-1064.34 h60
  text ".Print_Time" at 3848.5,-1064.34 h60
  text "TEXAS INSTRUMENTS" at 5113,-1064.34 h60
M6 Assembly Bottom:
  lines w10: -292.5,-727.33 6309.5,-727.33 ; -290.5,-930.67 6309.5,-930.67 ; 1115.5,-1140.5 1115.5,-937.67 ; 1737.5,-727.33 1737.5,-524 ; 2577.5,-727.33 2577.5,-524 ; 3844.5,-1134 3844.5,-524 ; 4733.5,-1134 6309,-1134 6309,-524 -292.5,-524 -292.5,-1134 2304.5,-1134 6309.5,-1134 6309.5,-524
  text "COMPONENTS MARKED 'DNP' SHOULD NOT BE POPULATED." at 6102,-318 h60
  text ".VariantName" at 5058,-434 h60
  text "ASSEMBLY VARIANT:" at 6097,-434 h60
  text ".VersionControl_RevNumber" at 1035.5,-656.17 h60
  text "SVN REV:" at 1541.5,-656.17 h60
  text ".PCB_Rev" at 2088,-656.17 h60
  text "REV:" at 2379.5,-656.17 h60
  text ".PRJ_Number" at 3224,-656.17 h60
  text "BOARD #:" at 3769.5,-656.17 h60
  text "PCB VIEWED FROM BOTTOM SIDE" at 6246,-656.17 h60
  text ".TID" at 3224,-859.5 h60
  text "TID #:" at 3769.5,-859.5 h60
  text "TEXAS INSTRUMENTS" at 904.5,-1064.84 h60
  text ".Print_Time" at 2169,-1064.84 h60
  text ".Print_Date" at 2898,-1064.84 h60
  text "GENERATED    :" at 3767.5,-1064.84 h60
  text ".plot_File_Name" at 5440.5,-1064.84 h60
  text "PLOT NAME =" at 6246,-1064.84 h60
M9 Title Sheet:
  drawing of 57 lines, arcs and shapes, not listed
  text "1" at 739.84,8036.5 h70
  text "2" at 3235.5,8036.5 h70
  text "3" at 5724.84,8036.5 h70
  text "4" at 8231.51,8036.5 h70
  text "5" at 10730.5,8036.5 h70
  text "6" at 13235.5,8036.5 h70
  text "A" at -416.5,6893.5 h70
  text "A" at 14383.5,6893.5 h70
  text "B" at -416.5,4513.5 h70
  text "B" at 14383.5,4513.5 h70
  text "C" at -416.5,2138.5 h70
  text "C" at 14383.5,2138.5 h70
  text "PROJECT TITLE:" at 11343.5,277.5 h45
  text ".PRJ_Title" at 11393.5,144.17 h70
  text "DESIGNED FOR:" at 11343.5,-23.5 h45
  text ".PRJ_Customer" at 11393.5,-163.5 h70
  text "D" at -416.5,-231.5 h70
  text "D" at 14383.5,-231.5 h70
  text "FILE NAME:" at 11343.5,-323.5 h45
  text ".PCB_File_Name_No_Path" at 11393.5,-443.5 h70
  text "Texas Instruments (TI) and/or its licensors do not warrant the accuracy or completeness of this specification" at 6374,-605.34 h45
  text "ENGINEER:" at 11343.5,-613.5 h45
  text "LAYOUT BY:" at 12848.5,-613.5 h45
  text "or any information contained therein. TI and/or its licensors do not warrant that this design will meet" at 6329.01,-718 h45
  text ".PRJ_Engineer" at 11393.5,-768.49 h70
  text ".PCB_Layout" at 12899,-768.49 h70
  text "the specifications, will be suitable for your application or fit for any particular purpose, or will operate in" at 6329.01,-830.67 h45
  text ".Layer_Name" at 577,-858.49 h60
  text "ALTIUM DESIGNER VERSION:" at 12848.5,-923.5 h45
  text "an implementation. TI and/or its licensors do not warrant that the design is production worthy. You should" at 6329.01,-943.33 h45
  text "completely validate and test your design implementation to confirm the system functionality for your application." at 6374,-1056 h45
  text ".print_Scale" at 11393.5,-1056.83 h70
  text ".Application_BuildNumber" at 12899,-1056.83 h70
  text "1" at 739.84,-1263.5 h70
  text "2" at 3235.5,-1263.5 h70
  text "3" at 5724.84,-1263.5 h70
  text "4" at 8231.51,-1263.5 h70
  text "5" at 10730.5,-1263.5 h70
  text "6" at 13235.5,-1263.5 h70
M10 Fab Notes:
  drawing of 173 lines, arcs and shapes, not listed
  text "DESIGN INFORMATION" at 12377.02,6201 h60
  text "MIN. TRACK WIDTH:" at 11732.46,6021 h60
  text "8" at 12828.7,6021 h60
  text "MIL" at 12983.46,6021 h60
  text "MIN. CLEARANCE:" at 11732.46,5889 h60
  text "0.2" at 12768.7,5889 h60
  text "mm" at 12983.46,5889 h60
  text "MIN. VIA PAD SIZE:" at 11732.46,5757 h60
  text "24" at 12798.71,5757 h60
  text "MIL" at 12983.46,5757 h60
  text "0.05mm (2MIL)" at 12427.46,5615.29 h60
  text "MINIMUM ANNULAR RING" at 11403.23,5611 h60
  text "EXTERNAL" at 13135.46,5611 h60
  text "PER" at 11603.23,5493 h60
  text "IPC-D-275 CLASS 2 LEVEL C" at 11823.23,5493 h60
  text "MIL, HOLES" at 13311.46,5380.71 h60
  text "+/-" at 12919,5380 h60
  text "+/-" at 13773,5380 h60
  text "REGISTRATION TOLERANCES:" at 11403.23,5375 h60
  text "METAL" at 12603,5375 h60
  text "5" at 13179.2,5375 h60
  text "3" at 14012.2,5375 h60
  text "MIL" at 14128.46,5375 h60
  text "+/-" at 13773,5262 h60
  text "HOLE SIZE TOLERANCE (UNLESS OTHERWISE SPECIFIED):" at 11403.23,5257 h60
  text "3" at 14012.2,5257 h60
  text "MIL" at 14128.46,5257 h60
  text "MATERIAL:" at 11328.46,5047.54 h60
  text "FR-4 High Tg" at 12314.9,4907.21 h60
  text "FR-408" at 11749.46,4898.64 h60
  text "OTHER" at 13237.46,4898.64 h60
  text "X" at 12160,4895 h60
  text "62 MIL (1.6mm) +/-10%" at 12069.56,4735.92 h60
  text "THICKNESS:" at 11403.23,4731.64 h60
  text "X" at 11941.4,4731.64 h60
  text "OTHER" at 13354.46,4731.64 h60
  text "TOLERANCE:" at 11403.23,4573.64 h60
  text "X" at 12242.53,4573.64 h60
  text "ANSI IPC-6012 TYPE 3 CLASS 2" at 12429.48,4573.64 h60
  text "OTHER +/-" at 12429.46,4417.64 h60
  text "BOW & TWIST:" at 11403.23,4260.64 h60
  text "X" at 12242.53,4260.64 h60
  text "ANSI IPC-6012 TYPE 3 CLASS 2" at 12429.48,4260.64 h60
  text "OTHER +/-" at 12429.46,4102.13 h60
  text "DRILLING:" at 11328.46,3963.64 h60
  text "REFERENCE:" at 11403.23,3846.64 h60
  text "X" at 12051.46,3846.64 h60
  text "AS SHOWN" at 12238.46,3846.64 h60
  text "X" at 12952.46,3846.64 h60
  text "NC_DRILL FILES" at 13089.46,3846.64 h60
  text "PTH COPPER THICKNESS:" at 11403.23,3688.64 h60
  text "X" at 12533.46,3688.64 h60
  text "20-30 um" at 12670.46,3688.64 h60
  text "OTHER" at 13387.46,3688.64 h60
  text "BOARD FINISH:" at 11328.46,3529.64 h60
  text "SILKSCREEN:" at 11483.68,3411.64 h60
  text "X" at 12432.46,3411.64 h60
  text "TOP" at 12558.46,3411.64 h60
  text "X" at 12942.46,3411.64 h60
  text "BOTTOM" at 13069.46,3411.64 h60
  text "SILKSCREEN COLOR:" at 11483.68,3244.64 h60
  text "X" at 12431.42,3244.64 h60
  text "WHITE" at 12558.46,3244.64 h60
  text "OTHER" at 13069.46,3244.64 h60
  text "X" at 12562.42,3085.44 h60
  text "GREEN" at 12689.46,3085.44 h60
  text "OTHER" at 13307.46,3085.44 h60
  text "SOLDER RESIST COLOR:" at 11483.68,3074.64 h60
  text "X" at 12562.42,2915.44 h60
  text "MATTE" at 12689.46,2915.44 h60
  text "SEMI-GLOSS" at 13307,2914.8 h60
  text "IMMERSION GOLD (ENIG)" at 12389.46,2726.92 h60
  text "ENEPIG" at 13727,2723.64 h60
  text "SURFACE FINISH:" at 11328.46,2722.64 h60
  text "X" at 12202.51,2722.64 h60
  text "IMM. TIN/SILVER OR EQUIV" at 11658,2565.64 h60
  text "OTHER" at 13089.46,2565.64 h60
  text "ARRAY/PANEL:" at 11328.46,2386.64 h60
  text "CUT AND TRIM PER M1 BOARD OUTLINE" at 12389.46,2382.35 h60
  text "N.C. ROUTE" at 12389.46,2230.64 h60
  text "X" at 13068.46,2230.64 h60
  text "V. SCORE" at 13255.46,2230.64 h60
  text "CERTIFICATION:" at 11328.46,2093.64 h60
  text "MATERIALS AND WORKMANSHIP FOR ALL PCBS" at 12053.46,2093.64 h60
  text "TO MEET OR EXCEED THE REQUIREMENTS OF:" at 12053.46,1995.64 h60
  text "X" at 11679.96,1859.13 h60
  text "ANSI IPC-A-600F CLASS ->" at 11818.96,1859.13 h60
  text "X" at 13458.02,1859.13 h60
  text "2" at 13576.96,1859.14 h60
  text "1" at 13261.96,1857.64 h60
  text "3" at 13930.96,1857.64 h60
  text "X" at 12494.02,1699.64 h60
  text "RoHS" at 12630.96,1699.64 h60
  text "OTHER" at 13275.36,1699.64 h60
  text "PER ORDER" at 13672.42,1699.64 h60
  text "ALL BOARDS MUST MEET OR EXCEED UL94-V0 REQUIREMENTS." at 11356,1534 h60
  text "PCB MUST BEAR THE UL94V-0 UL REGISTERED MATERIAL ID NUMBER" at 11356,1414 h60
  text "ADDITIONAL REQUIREMENTS:" at 11328.46,1240.64 h60
  text "MICROSECTION:" at 11403.23,1125.64 h60
  text "YES" at 12308.96,1125.64 h60
  text "REQUIRED" at 13170.46,969.49 h60
  text "BARE BOARD ELEC. TEST:" at 11403.23,966.64 h60
  text "NONE" at 12708.96,966.64 h60
  text "X" at 13043.46,966.64 h60
  text "PER ORDER" at 13762.46,966.64 h60
  text ".Layer_Name" at 577,-858.49 h60
M11 Gerber Information:
  lines w10: -292,-930.17 6308,-930.17 ; -292,-726.83 6310,-726.83 ; -292,-523.5 -292,-1133.5 3713,-1133.5 6310,-1133.5 6310,-523.5 -291.5,-523.5 -291.5,-1133.5 1284,-1133.5 ; 2173,-1133.5 2173,-523.5 ; 3440,-726.83 3440,-523.5 ; 4280,-726.83 4280,-523.5 ; 4902,-1140 4902,-937.17
  text "ALL ARTWORK VIEWED FROM TOP SIDE" at -228.5,-655.67 h60
  text "BOARD #:" at 2248,-655.67 h60
  text ".PRJ_Number" at 2793.5,-655.67 h60
  text "REV:" at 3638,-655.67 h60
  text ".PCB_Rev" at 3929.5,-655.67 h60
  text "SVN REV:" at 4476,-655.67 h60
  text ".VersionControl_RevNumber" at 4982,-655.67 h60
  text "LAYER NAME =" at -228.5,-858.49 h60
  text "TID #:" at 2248,-859 h60
  text ".TID" at 2793.5,-859 h60
  text "PLOT NAME =" at -228.5,-1064.34 h60
  text ".plot_File_Name" at 577,-1064.34 h60
  text "GENERATED    :" at 2250,-1064.34 h60
  text ".Print_Date" at 3119.5,-1064.34 h60
  text ".Print_Time" at 3848.5,-1064.34 h60
  text "TEXAS INSTRUMENTS" at 5113,-1064.34 h60
M12 Stackup:
  drawing of 191 lines, arcs and shapes, not listed
  text "Layer" at 9790.58,7830 h60
  text "Name" at 10200.49,7830 h60
  text "Material" at 11130.23,7830 h60
  text "Thickness" at 11990,7830 h60
  text "Constant" at 12639.84,7830 h60
  text "Board Layer Stack" at 13209.7,7830 h60
  text "1" at 9790.58,7710 h60
  text "Top Overlay" at 10200.49,7710 h60
  text "2" at 9790.58,7590 h60
  text "Top Solder" at 10200.49,7590 h60
  text "Solder Resist" at 11130.23,7590 h60
  text "0.40mil" at 11990,7590 h60
  text "3.5" at 12639.84,7590 h60
  text "3" at 9790.58,7470 h60
  text "Top Layer" at 10200.49,7470 h60
  text "Copper" at 11130.23,7470 h60
  text "1.40mil" at 11990,7470 h60
  text "4" at 9790.58,7350 h60
  text "Dielectric1" at 10200.49,7350 h60
  text "FR-4" at 11130.23,7350 h60
  text "59.20mil" at 11990,7350 h60
  text "4.8" at 12639.84,7350 h60
  text "5" at 9790.58,7230 h60
  text "Bottom Layer" at 10200.49,7230 h60
  text "Copper" at 11130.23,7230 h60
  text "1.40mil" at 11990,7230 h60
  text "6" at 9790.58,7110 h60
  text "Bottom Solder" at 10200.49,7110 h60
  text "Solder Resist" at 11130.23,7110 h60
  text "0.40mil" at 11990,7110 h60
  text "3.5" at 12639.84,7110 h60
  text "7" at 9790.58,6990 h60
  text "Bottom Overlay" at 10200.49,6990 h60
  text ".Layer_Name" at 577,-858.49 h60
M13 Component Bodies Top:
  text ".Layer_Name" at 577,-858.49 h60
M14 Component Bodies Bottom:
  text ".Layer_Name" at 577,-858.49 h60
M15 Courtyards Top:
  text ".Layer_Name" at 577,-858.49 h60
M16 Courtyards Bottom:
  text ".Layer_Name" at 577,-858.49 h60
Drill Drawing:
  text ".Layer_Name" at 577,-858.49 h60

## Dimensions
0,0 to 2800,3100 on M2 Board Dimensions
0,0 to 0,0 on M2 Board Dimensions
0,-400 to 1000,-400 on M2 Board Dimensions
